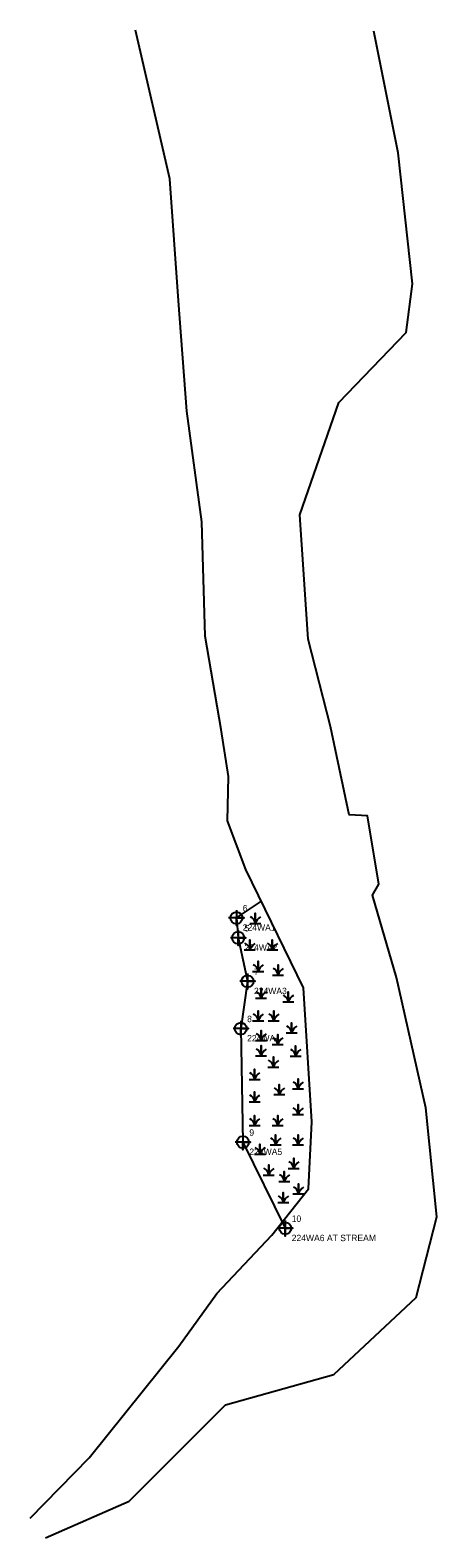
# Model space of a CAD drawing. Extents: x 2141820 to 2141979, y 1011654 to 1012242.
import ezdxf

# ---------------------------------------------------------------- set-up
doc = ezdxf.new("R2010")
doc.units = 0
for name, color, linetype in [('Exist Environmental Wetland Boundary', 7, 'Continuous'), ('Exist Environmental Wetland Boundary Cogo Comment', 7, 'Continuous'), ('Exist Environmental Wetland Boundary Cogo Number', 7, 'Continuous'), ('Exist Environmental Wetland Boundary Cogo Point CELL', 7, 'Continuous'), ('Exist Hydro Jurisdictional Stream or Body of Water Mitigable', 7, 'Continuous'), ('Exist Hydro Swamp or Marsh', 7, 'Continuous')]:
    doc.layers.add(name, color=color, linetype=linetype)

msp = doc.modelspace()

# ---------------------------------------------------------------- linework, layer by layer
at = {"layer": 'Exist Environmental Wetland Boundary'}
msp.add_line((2141900.31, 1011895.8), (2141910.1, 1011902.37), dxfattribs=at)
msp.add_lwpolyline([(2141900.31, 1011895.8), (2141901, 1011888.01), (2141904.69, 1011871.06), (2141902.02, 1011852.65), (2141902.88, 1011808.36), (2141919.41, 1011774.76)], dxfattribs=at)
at = {"layer": 'Exist Environmental Wetland Boundary Cogo Point CELL'}
for points in [[(2141900.31, 1011898.8), (2141900.31, 1011892.8), (2141900.31, 1011895.8), (2141903.31, 1011895.8), (2141897.31, 1011895.8)], [(2141901, 1011891.01), (2141901, 1011885.01), (2141901, 1011888.01), (2141904, 1011888.01), (2141898, 1011888.01)], [(2141904.69, 1011874.06), (2141904.69, 1011868.06), (2141904.69, 1011871.06), (2141907.69, 1011871.06), (2141901.69, 1011871.06)], [(2141902.02, 1011855.65), (2141902.02, 1011849.65), (2141902.02, 1011852.65), (2141905.02, 1011852.65), (2141899.02, 1011852.65)], [(2141902.88, 1011811.36), (2141902.88, 1011805.36), (2141902.88, 1011808.36), (2141905.88, 1011808.36), (2141899.88, 1011808.36)], [(2141919.41, 1011777.76), (2141919.41, 1011771.76), (2141919.41, 1011774.76), (2141922.41, 1011774.76), (2141916.41, 1011774.76)]]:
    msp.add_lwpolyline(points, dxfattribs=at)
for centre in [(2141900.31, 1011895.8), (2141901, 1011888.01), (2141904.69, 1011871.06), (2141902.02, 1011852.65), (2141902.88, 1011808.36), (2141919.41, 1011774.76)]:
    msp.add_circle(centre, 2.34, dxfattribs=at)
at = {"layer": 'Exist Hydro Jurisdictional Stream or Body of Water Mitigable'}
for points in [[(2141819.83, 1011661.76), (2141842.82, 1011685.28), (2141877.88, 1011728.84), (2141892.74, 1011749.38), (2141914.17, 1011772.04), (2141928.49, 1011790.1), (2141929.77, 1011816.28), (2141926.55, 1011868.47), (2141904.02, 1011914.67), (2141896.86, 1011933.64), (2141897.25, 1011950.92), (2141894.44, 1011969.24), (2141888.18, 1012005.59), (2141886.89, 1012050.26), (2141881.01, 1012093.36), (2141877.78, 1012136.41), (2141874.3, 1012183.91), (2141860.92, 1012241.92)], [(2141825.79, 1011654.08), (2141858.45, 1011668.42), (2141896.14, 1011705.88), (2141938.41, 1011717.79), (2141970.51, 1011747.74), (2141978.57, 1011779.18), (2141974.29, 1011821.74), (2141962.81, 1011872.51), (2141953.41, 1011904.64), (2141955.91, 1011908.95), (2141951.54, 1011935.53), (2141944.28, 1011935.92), (2141937.03, 1011970.39), (2141928.32, 1012004.51), (2141925.08, 1012052.89), (2141940.28, 1012096.68), (2141966.64, 1012123.99), (2141969.11, 1012143.02), (2141963.5, 1012194.09), (2141953.93, 1012241.54)]]:
    msp.add_lwpolyline(points, dxfattribs=at)
at = {"layer": 'Exist Hydro Swamp or Marsh'}
for p, q in [((2141907.69, 1011895.43), (2141907.69, 1011895.43)), ((2141905.57, 1011885.08), (2141905.57, 1011885.08)), ((2141914.35, 1011885.08), (2141914.35, 1011885.08)), ((2141908.83, 1011876.72), (2141908.83, 1011876.72)), ((2141916.62, 1011875.3), (2141916.62, 1011875.3)), ((2141909.96, 1011866.23), (2141909.96, 1011866.23)), ((2141920.59, 1011864.81), (2141920.59, 1011864.81)), ((2141908.83, 1011857.44), (2141908.83, 1011857.44)), ((2141914.92, 1011857.44), (2141914.92, 1011857.44)), ((2141909.96, 1011849.78), (2141909.96, 1011849.78)), ((2141916.48, 1011848.22), (2141916.48, 1011848.22)), ((2141921.86, 1011852.76), (2141921.86, 1011852.76)), ((2141909.96, 1011843.83), (2141909.96, 1011843.83)), ((2141923.42, 1011843.69), (2141923.42, 1011843.69)), ((2141914.78, 1011839.44), (2141914.78, 1011839.44)), ((2141907.41, 1011834.62), (2141907.41, 1011834.62)), ((2141924.41, 1011830.93), (2141924.41, 1011830.93)), ((2141907.41, 1011825.83), (2141907.41, 1011825.83)), ((2141917.04, 1011828.66), (2141917.04, 1011828.66)), ((2141924.41, 1011820.87), (2141924.41, 1011820.87)), ((2141907.41, 1011816.61), (2141907.41, 1011816.61)), ((2141916.48, 1011816.61), (2141916.48, 1011816.61)), ((2141915.63, 1011809.07), (2141915.63, 1011809.07)), ((2141924.41, 1011809.07), (2141924.41, 1011809.07)), ((2141909.53, 1011805.42), (2141909.53, 1011805.42)), ((2141912.93, 1011797.34), (2141912.93, 1011797.34)), ((2141922.71, 1011799.89), (2141922.71, 1011799.89)), ((2141919.03, 1011794.79), (2141919.03, 1011794.79)), ((2141924.55, 1011789.97), (2141924.55, 1011789.97)), ((2141918.6, 1011786.56), (2141918.6, 1011786.56))]:
    msp.add_line(p, q, dxfattribs=at)
for points in [[(2141905.54, 1011893.64), (2141907.69, 1011893.64), (2141907.69, 1011897.59), (2141907.69, 1011893.64), (2141909.84, 1011893.64)], [(2141903.42, 1011883.3), (2141905.57, 1011883.3), (2141905.57, 1011887.24), (2141905.57, 1011883.3), (2141907.72, 1011883.3)], [(2141912.2, 1011883.3), (2141914.35, 1011883.3), (2141914.35, 1011887.24), (2141914.35, 1011883.3), (2141916.5, 1011883.3)], [(2141906.68, 1011874.93), (2141908.83, 1011874.93), (2141908.83, 1011878.88), (2141908.83, 1011874.93), (2141910.98, 1011874.93)], [(2141914.47, 1011873.52), (2141916.62, 1011873.52), (2141916.62, 1011877.46), (2141916.62, 1011873.52), (2141918.77, 1011873.52)], [(2141907.81, 1011864.44), (2141909.96, 1011864.44), (2141909.96, 1011868.39), (2141909.96, 1011864.44), (2141912.11, 1011864.44)], [(2141918.44, 1011863.03), (2141920.59, 1011863.03), (2141920.59, 1011866.97), (2141920.59, 1011863.03), (2141922.74, 1011863.03)], [(2141906.68, 1011855.65), (2141908.83, 1011855.65), (2141908.83, 1011859.6), (2141908.83, 1011855.65), (2141910.98, 1011855.65)], [(2141912.77, 1011855.65), (2141914.92, 1011855.65), (2141914.92, 1011859.6), (2141914.92, 1011855.65), (2141917.07, 1011855.65)], [(2141919.71, 1011850.98), (2141921.86, 1011850.98), (2141921.86, 1011854.92), (2141921.86, 1011850.98), (2141924.01, 1011850.98)], [(2141907.81, 1011848), (2141909.96, 1011848), (2141909.96, 1011851.95), (2141909.96, 1011848), (2141912.11, 1011848)], [(2141914.33, 1011846.44), (2141916.48, 1011846.44), (2141916.48, 1011850.39), (2141916.48, 1011846.44), (2141918.63, 1011846.44)], [(2141907.81, 1011842.05), (2141909.96, 1011842.05), (2141909.96, 1011845.99), (2141909.96, 1011842.05), (2141912.11, 1011842.05)], [(2141921.27, 1011841.91), (2141923.42, 1011841.91), (2141923.42, 1011845.85), (2141923.42, 1011841.91), (2141925.57, 1011841.91)], [(2141905.26, 1011832.83), (2141907.41, 1011832.83), (2141907.41, 1011836.78), (2141907.41, 1011832.83), (2141909.56, 1011832.83)], [(2141912.63, 1011837.65), (2141914.78, 1011837.65), (2141914.78, 1011841.6), (2141914.78, 1011837.65), (2141916.93, 1011837.65)], [(2141914.89, 1011826.88), (2141917.04, 1011826.88), (2141917.04, 1011830.83), (2141917.04, 1011826.88), (2141919.19, 1011826.88)], [(2141922.26, 1011829.15), (2141924.41, 1011829.15), (2141924.41, 1011833.09), (2141924.41, 1011829.15), (2141926.56, 1011829.15)], [(2141905.26, 1011824.05), (2141907.41, 1011824.05), (2141907.41, 1011827.99), (2141907.41, 1011824.05), (2141909.56, 1011824.05)], [(2141905.26, 1011814.83), (2141907.41, 1011814.83), (2141907.41, 1011818.78), (2141907.41, 1011814.83), (2141909.56, 1011814.83)], [(2141914.33, 1011814.83), (2141916.48, 1011814.83), (2141916.48, 1011818.78), (2141916.48, 1011814.83), (2141918.63, 1011814.83)], [(2141922.26, 1011819.08), (2141924.41, 1011819.08), (2141924.41, 1011823.03), (2141924.41, 1011819.08), (2141926.56, 1011819.08)], [(2141907.38, 1011803.63), (2141909.53, 1011803.63), (2141909.53, 1011807.58), (2141909.53, 1011803.63), (2141911.68, 1011803.63)], [(2141913.48, 1011807.29), (2141915.63, 1011807.29), (2141915.63, 1011811.24), (2141915.63, 1011807.29), (2141917.78, 1011807.29)], [(2141922.26, 1011807.29), (2141924.41, 1011807.29), (2141924.41, 1011811.24), (2141924.41, 1011807.29), (2141926.56, 1011807.29)], [(2141920.56, 1011798.11), (2141922.71, 1011798.11), (2141922.71, 1011802.05), (2141922.71, 1011798.11), (2141924.86, 1011798.11)], [(2141910.78, 1011795.55), (2141912.94, 1011795.55), (2141912.94, 1011799.5), (2141912.94, 1011795.55), (2141915.09, 1011795.55)], [(2141916.88, 1011793), (2141919.03, 1011793), (2141919.03, 1011796.95), (2141919.03, 1011793), (2141921.18, 1011793)], [(2141922.4, 1011788.18), (2141924.55, 1011788.18), (2141924.55, 1011792.13), (2141924.55, 1011788.18), (2141926.7, 1011788.18)], [(2141916.45, 1011784.78), (2141918.6, 1011784.78), (2141918.6, 1011788.73), (2141918.6, 1011784.78), (2141920.75, 1011784.78)]]:
    msp.add_lwpolyline(points, dxfattribs=at)
for centre, radius, start, end in [((2141904.63, 1011893.42), 3.07, 4.14034, 67.53497), ((2141912.25, 1011892.13), 4.81, 122.12745, 161.62219), ((2141902.5, 1011883.07), 3.07, 4.14034, 67.53497), ((2141910.13, 1011881.78), 4.81, 122.12745, 161.62219), ((2141911.29, 1011883.07), 3.07, 4.14034, 67.53497), ((2141918.91, 1011881.78), 4.81, 122.12745, 161.62219), ((2141905.76, 1011874.71), 3.07, 4.14034, 67.53497), ((2141913.39, 1011873.42), 4.81, 122.12745, 161.62219), ((2141913.55, 1011873.29), 3.07, 4.14034, 67.53497), ((2141921.18, 1011872), 4.81, 122.12745, 161.62219), ((2141906.89, 1011864.22), 3.07, 4.14034, 67.53497), ((2141914.52, 1011862.93), 4.81, 122.12745, 161.62219), ((2141917.52, 1011862.8), 3.07, 4.14034, 67.53497), ((2141925.15, 1011861.51), 4.81, 122.12745, 161.62219), ((2141905.76, 1011855.43), 3.07, 4.14034, 67.53497), ((2141913.39, 1011854.14), 4.81, 122.12745, 161.62219), ((2141911.85, 1011855.43), 3.07, 4.14034, 67.53497), ((2141919.48, 1011854.14), 4.81, 122.12745, 161.62219), ((2141906.89, 1011847.78), 3.07, 4.14034, 67.53497), ((2141914.52, 1011846.49), 4.81, 122.12745, 161.62219), ((2141913.41, 1011846.22), 3.07, 4.14034, 67.53497), ((2141921.04, 1011844.93), 4.81, 122.12745, 161.62219), ((2141918.8, 1011850.76), 3.07, 4.14034, 67.53497), ((2141926.42, 1011849.46), 4.81, 122.12745, 161.62219), ((2141906.89, 1011841.83), 3.07, 4.14034, 67.53497), ((2141914.52, 1011840.53), 4.81, 122.12745, 161.62219), ((2141920.35, 1011841.68), 3.07, 4.14034, 67.53497), ((2141927.98, 1011840.39), 4.81, 122.12745, 161.62219), ((2141911.71, 1011837.43), 3.07, 4.14034, 67.53497), ((2141919.34, 1011836.14), 4.81, 122.12745, 161.62219), ((2141904.34, 1011832.61), 3.07, 4.14034, 67.53497), ((2141911.97, 1011831.32), 4.81, 122.12745, 161.62219), ((2141921.35, 1011828.93), 3.07, 4.14034, 67.53497), ((2141928.97, 1011827.63), 4.81, 122.12745, 161.62219), ((2141904.34, 1011823.82), 3.07, 4.14034, 67.53497), ((2141911.97, 1011822.53), 4.81, 122.12745, 161.62219), ((2141913.98, 1011826.66), 3.07, 4.14034, 67.53497), ((2141921.6, 1011825.37), 4.81, 122.12745, 161.62219), ((2141921.35, 1011818.86), 3.07, 4.14034, 67.53497), ((2141928.97, 1011817.57), 4.81, 122.12745, 161.62219), ((2141904.34, 1011814.61), 3.07, 4.14034, 67.53497), ((2141911.97, 1011813.32), 4.81, 122.12745, 161.62219), ((2141913.41, 1011814.61), 3.07, 4.14034, 67.53497), ((2141921.04, 1011813.32), 4.81, 122.12745, 161.62219), ((2141912.56, 1011807.07), 3.07, 4.14034, 67.53497), ((2141920.19, 1011805.78), 4.81, 122.12745, 161.62219), ((2141921.35, 1011807.07), 3.07, 4.14034, 67.53497), ((2141928.97, 1011805.78), 4.81, 122.12745, 161.62219), ((2141906.47, 1011803.41), 3.07, 4.14034, 67.53497), ((2141914.1, 1011802.12), 4.81, 122.12745, 161.62219), ((2141909.87, 1011795.33), 3.07, 4.14034, 67.53497), ((2141917.5, 1011794.04), 4.81, 122.12745, 161.62219), ((2141915.96, 1011792.78), 3.07, 4.14034, 67.53497), ((2141923.59, 1011791.49), 4.81, 122.12745, 161.62219), ((2141919.65, 1011797.88), 3.07, 4.14034, 67.53497), ((2141927.27, 1011796.59), 4.81, 122.12745, 161.62219), ((2141921.49, 1011787.96), 3.07, 4.14034, 67.53497), ((2141929.11, 1011786.67), 4.81, 122.12745, 161.62219), ((2141915.54, 1011784.56), 3.07, 4.14034, 67.53497), ((2141923.16, 1011783.27), 4.81, 122.12745, 161.62219)]:
    msp.add_arc(centre, radius, start, end, dxfattribs=at)

# ---------------------------------------------------------------- texts
at = {"layer": 'Exist Environmental Wetland Boundary Cogo Comment'}
for s, p in [('224WA1', (2141902.81, 1011890.8)), ('224WA2', (2141903.5, 1011883.01)), ('224WA3', (2141907.19, 1011866.06)), ('224WA4', (2141904.52, 1011847.65)), ('224WA5', (2141905.38, 1011803.36)), ('224WA6 AT STREAM', (2141921.91, 1011769.76))]:
    msp.add_text(s, height=2.5, dxfattribs=at).set_placement(p)
at = {"layer": 'Exist Environmental Wetland Boundary Cogo Number'}
for s, p in [('6', (2141902.81, 1011898.3)), ('5', (2141903.5, 1011890.51)), ('7', (2141907.19, 1011873.56)), ('8', (2141904.52, 1011855.15)), ('9', (2141905.38, 1011810.86)), ('10', (2141921.91, 1011777.26))]:
    msp.add_text(s, height=2.5, dxfattribs=at).set_placement(p)

doc.saveas('drawing.dxf')
